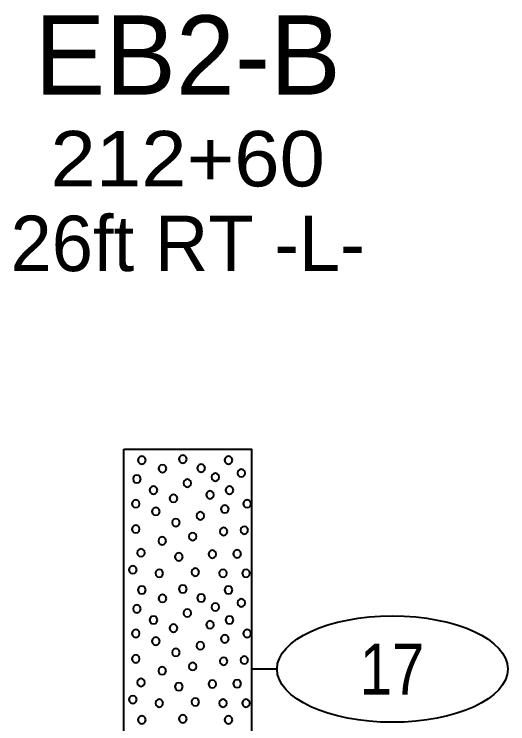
# Model space of a CAD drawing. Extents: x -582 to 653, y -817 to -3.
# Drawn here: x -482.55 to -472.9, y -185.68 to -171.8 of the extents above; entities that cross this region are included whole.
import ezdxf
from ezdxf.enums import TextEntityAlignment as Align

# ---------------------------------------------------------------- set-up
doc = ezdxf.new("R2010")
doc.units = 0
doc.header["$LTSCALE"] = 0.4
doc.layers.add('27', color=7, linetype='Continuous', lineweight=40)

msp = doc.modelspace()

# ---------------------------------------------------------------- linework, layer by layer
at = {"layer": '27'}
msp.add_line((-477.4109, -184.608), (-477.9109, -184.608), dxfattribs=at)
for points in [[(-480.4109, -180.308), (-477.9109, -180.308), (-477.9109, -206.808), (-480.4109, -206.808)], [(-479.979, -180.5207), (-479.9892, -180.4826), (-480.0171, -180.4547), (-480.0552, -180.4445), (-480.0933, -180.4547), (-480.1212, -180.4826), (-480.1314, -180.5207), (-480.1212, -180.5588), (-480.0933, -180.5867), (-480.0552, -180.5969), (-480.0171, -180.5867), (-479.9892, -180.5588)], [(-479.1781, -180.5011), (-479.1883, -180.463), (-479.2162, -180.4351), (-479.2543, -180.4249), (-479.2924, -180.4351), (-479.3202, -180.463), (-479.3305, -180.5011), (-479.3202, -180.5392), (-479.2924, -180.5671), (-479.2543, -180.5773), (-479.2162, -180.5671), (-479.1883, -180.5392)], [(-478.2844, -180.5207), (-478.2946, -180.4826), (-478.3225, -180.4548), (-478.3606, -180.4445), (-478.3987, -180.4548), (-478.4266, -180.4826), (-478.4368, -180.5207), (-478.4266, -180.5588), (-478.3987, -180.5867), (-478.3606, -180.5969), (-478.3225, -180.5867), (-478.2946, -180.5588)], [(-479.5741, -180.686), (-479.5843, -180.6479), (-479.6122, -180.62), (-479.6503, -180.6098), (-479.6884, -180.62), (-479.7163, -180.6479), (-479.7265, -180.686), (-479.7163, -180.7241), (-479.6884, -180.7519), (-479.6503, -180.7622), (-479.6122, -180.7519), (-479.5843, -180.7241)], [(-478.819, -180.677), (-478.8292, -180.6389), (-478.8571, -180.611), (-478.8952, -180.6008), (-478.9333, -180.611), (-478.9612, -180.6389), (-478.9714, -180.677), (-478.9612, -180.7151), (-478.9333, -180.743), (-478.8952, -180.7532), (-478.8571, -180.743), (-478.8292, -180.7151)], [(-478.0335, -180.7728), (-478.0438, -180.7347), (-478.0716, -180.7069), (-478.1097, -180.6966), (-478.1478, -180.7069), (-478.1757, -180.7347), (-478.1859, -180.7728), (-478.1757, -180.8109), (-478.1478, -180.8388), (-478.1097, -180.849), (-478.0716, -180.8388), (-478.0438, -180.8109)], [(-480.0752, -180.8885), (-480.0854, -180.8504), (-480.1133, -180.8225), (-480.1514, -180.8123), (-480.1895, -180.8225), (-480.2174, -180.8504), (-480.2276, -180.8885), (-480.2174, -180.9266), (-480.1895, -180.9545), (-480.1514, -180.9647), (-480.1133, -180.9545), (-480.0854, -180.9266)], [(-479.0891, -180.9717), (-479.0993, -180.9336), (-479.1272, -180.9057), (-479.1653, -180.8955), (-479.2034, -180.9057), (-479.2313, -180.9336), (-479.2415, -180.9717), (-479.2313, -181.0098), (-479.2034, -181.0377), (-479.1653, -181.0479), (-479.1272, -181.0377), (-479.0993, -181.0098)], [(-478.5408, -180.8542), (-478.551, -180.8161), (-478.5789, -180.7882), (-478.617, -180.778), (-478.6551, -180.7882), (-478.683, -180.8161), (-478.6932, -180.8542), (-478.683, -180.8923), (-478.6551, -180.9202), (-478.617, -180.9304), (-478.5789, -180.9202), (-478.551, -180.8923)], [(-479.7523, -181.1072), (-479.7625, -181.0691), (-479.7904, -181.0412), (-479.8285, -181.031), (-479.8666, -181.0412), (-479.8945, -181.0691), (-479.9047, -181.1072), (-479.8945, -181.1453), (-479.8666, -181.1732), (-479.8285, -181.1834), (-479.7904, -181.1732), (-479.7625, -181.1453)], [(-478.2636, -181.1072), (-478.2739, -181.0691), (-478.3017, -181.0412), (-478.3398, -181.031), (-478.3779, -181.0412), (-478.4058, -181.0691), (-478.416, -181.1072), (-478.4058, -181.1453), (-478.3779, -181.1732), (-478.3398, -181.1834), (-478.3017, -181.1732), (-478.2739, -181.1453)], [(-478.645, -181.2), (-478.6552, -181.1619), (-478.6831, -181.134), (-478.7212, -181.1238), (-478.7593, -181.134), (-478.7872, -181.1619), (-478.7974, -181.2), (-478.7872, -181.2381), (-478.7593, -181.266), (-478.7212, -181.2762), (-478.6831, -181.266), (-478.6552, -181.2381)], [(-480.0981, -181.3729), (-480.1083, -181.3348), (-480.1362, -181.3069), (-480.1743, -181.2967), (-480.2124, -181.3069), (-480.2403, -181.3348), (-480.2505, -181.3729), (-480.2403, -181.411), (-480.2124, -181.4389), (-480.1743, -181.4491), (-480.1362, -181.4389), (-480.1083, -181.411)], [(-479.3607, -181.2686), (-479.371, -181.2305), (-479.3988, -181.2027), (-479.4369, -181.1924), (-479.475, -181.2027), (-479.5029, -181.2305), (-479.5131, -181.2686), (-479.5029, -181.3067), (-479.475, -181.3346), (-479.4369, -181.3448), (-479.3988, -181.3346), (-479.371, -181.3067)], [(-477.9179, -181.3729), (-477.9281, -181.3348), (-477.956, -181.3069), (-477.9941, -181.2967), (-478.0322, -181.3069), (-478.06, -181.3348), (-478.0703, -181.3729), (-478.06, -181.411), (-478.0322, -181.4389), (-477.9941, -181.4491), (-477.956, -181.4389), (-477.9281, -181.411)], [(-479.7065, -181.5229), (-479.7167, -181.4848), (-479.7446, -181.4569), (-479.7827, -181.4467), (-479.8208, -181.4569), (-479.8487, -181.4848), (-479.8589, -181.5229), (-479.8487, -181.561), (-479.8208, -181.5889), (-479.7827, -181.5991), (-479.7446, -181.5889), (-479.7167, -181.561)], [(-478.3564, -181.4771), (-478.3667, -181.439), (-478.3945, -181.4111), (-478.4326, -181.4009), (-478.4707, -181.4111), (-478.4986, -181.439), (-478.5088, -181.4771), (-478.4986, -181.5152), (-478.4707, -181.5431), (-478.4326, -181.5533), (-478.3945, -181.5431), (-478.3667, -181.5152)], [(-478.8344, -181.6106), (-478.8447, -181.5725), (-478.8725, -181.5446), (-478.9106, -181.5344), (-478.9487, -181.5446), (-478.9766, -181.5725), (-478.9868, -181.6106), (-478.9766, -181.6487), (-478.9487, -181.6766), (-478.9106, -181.6868), (-478.8725, -181.6766), (-478.8447, -181.6487)], [(-479.3124, -181.7416), (-479.3226, -181.7035), (-479.3505, -181.6756), (-479.3886, -181.6654), (-479.4267, -181.6756), (-479.4546, -181.7035), (-479.4648, -181.7416), (-479.4546, -181.7797), (-479.4267, -181.8075), (-479.3886, -181.8178), (-479.3505, -181.8075), (-479.3226, -181.7797)], [(-480.0981, -181.8687), (-480.1083, -181.8306), (-480.1362, -181.8027), (-480.1743, -181.7925), (-480.2124, -181.8027), (-480.2403, -181.8306), (-480.2505, -181.8687), (-480.2403, -181.9068), (-480.2124, -181.9347), (-480.1743, -181.9449), (-480.1362, -181.9347), (-480.1083, -181.9068)], [(-478.3793, -181.9157), (-478.3895, -181.8776), (-478.4174, -181.8497), (-478.4555, -181.8395), (-478.4936, -181.8497), (-478.5215, -181.8776), (-478.5317, -181.9157), (-478.5215, -181.9538), (-478.4936, -181.9817), (-478.4555, -181.9919), (-478.4174, -181.9817), (-478.3895, -181.9538)], [(-477.9751, -181.8916), (-477.9853, -181.8535), (-478.0132, -181.8256), (-478.0513, -181.8154), (-478.0894, -181.8256), (-478.1173, -181.8535), (-478.1275, -181.8916), (-478.1173, -181.9297), (-478.0894, -181.9576), (-478.0513, -181.9678), (-478.0132, -181.9576), (-477.9853, -181.9297)], [(-478.9845, -182.0161), (-478.9947, -181.978), (-479.0226, -181.9502), (-479.0607, -181.9399), (-479.0988, -181.9502), (-479.1266, -181.978), (-479.1369, -182.0161), (-479.1266, -182.0542), (-479.0988, -182.0821), (-479.0607, -182.0923), (-479.0226, -182.0821), (-478.9947, -182.0542)], [(-479.5794, -182.1001), (-479.5896, -182.062), (-479.6175, -182.0341), (-479.6556, -182.0239), (-479.6937, -182.0341), (-479.7216, -182.062), (-479.7318, -182.1001), (-479.7216, -182.1382), (-479.6937, -182.166), (-479.6556, -182.1763), (-479.6175, -182.166), (-479.5896, -182.1382)], [(-479.9951, -182.3314), (-480.0053, -182.2933), (-480.0332, -182.2654), (-480.0713, -182.2552), (-480.1094, -182.2654), (-480.1373, -182.2933), (-480.1475, -182.3314), (-480.1373, -182.3695), (-480.1094, -182.3974), (-480.0713, -182.4076), (-480.0332, -182.3974), (-480.0053, -182.3695)], [(-478.5993, -182.3607), (-478.6095, -182.3226), (-478.6374, -182.2947), (-478.6755, -182.2845), (-478.7136, -182.2947), (-478.7414, -182.3226), (-478.7517, -182.3607), (-478.7414, -182.3988), (-478.7136, -182.4267), (-478.6755, -182.4369), (-478.6374, -182.4267), (-478.6095, -182.3988)], [(-478.1136, -182.353), (-478.1238, -182.3149), (-478.1517, -182.287), (-478.1898, -182.2768), (-478.2279, -182.287), (-478.2558, -182.3149), (-478.266, -182.353), (-478.2558, -182.3911), (-478.2279, -182.419), (-478.1898, -182.4292), (-478.1517, -182.419), (-478.1238, -182.3911)], [(-479.2565, -182.4115), (-479.2667, -182.3734), (-479.2946, -182.3455), (-479.3327, -182.3353), (-479.3708, -182.3455), (-479.3987, -182.3734), (-479.4089, -182.4115), (-479.3987, -182.4496), (-479.3708, -182.4775), (-479.3327, -182.4877), (-479.2946, -182.4775), (-479.2667, -182.4496)], [(-480.1566, -182.6645), (-480.1668, -182.6264), (-480.1947, -182.5985), (-480.2328, -182.5883), (-480.2709, -182.5985), (-480.2988, -182.6264), (-480.309, -182.6645), (-480.2988, -182.7026), (-480.2709, -182.7305), (-480.2328, -182.7407), (-480.1947, -182.7305), (-480.1668, -182.7026)], [(-479.6379, -182.7344), (-479.6481, -182.6963), (-479.676, -182.6684), (-479.7141, -182.6582), (-479.7522, -182.6684), (-479.7801, -182.6963), (-479.7903, -182.7344), (-479.7801, -182.7725), (-479.7522, -182.8004), (-479.7141, -182.8106), (-479.676, -182.8004), (-479.6481, -182.7725)], [(-478.9336, -182.7115), (-478.9438, -182.6734), (-478.9717, -182.6455), (-479.0098, -182.6353), (-479.0479, -182.6455), (-479.0758, -182.6734), (-479.086, -182.7115), (-479.0758, -182.7496), (-479.0479, -182.7775), (-479.0098, -182.7877), (-478.9717, -182.7775), (-478.9438, -182.7496)], [(-478.3908, -182.7344), (-478.401, -182.6963), (-478.4289, -182.6684), (-478.467, -182.6582), (-478.5051, -182.6684), (-478.533, -182.6963), (-478.5432, -182.7344), (-478.533, -182.7725), (-478.5051, -182.8004), (-478.467, -182.8106), (-478.4289, -182.8004), (-478.401, -182.7725)], [(-477.9407, -182.7344), (-477.9509, -182.6963), (-477.9788, -182.6684), (-478.0169, -182.6582), (-478.055, -182.6684), (-478.0829, -182.6963), (-478.0931, -182.7344), (-478.0829, -182.7725), (-478.055, -182.8004), (-478.0169, -182.8106), (-477.9788, -182.8004), (-477.9509, -182.7725)], [(-479.1781, -183.0411), (-479.1883, -183.003), (-479.2162, -182.9751), (-479.2543, -182.9649), (-479.2924, -182.9751), (-479.3202, -183.003), (-479.3305, -183.0411), (-479.3202, -183.0792), (-479.2924, -183.1071), (-479.2543, -183.1173), (-479.2162, -183.1071), (-479.1883, -183.0792)], [(-479.979, -183.0607), (-479.9892, -183.0226), (-480.0171, -182.9947), (-480.0552, -182.9845), (-480.0933, -182.9947), (-480.1212, -183.0226), (-480.1314, -183.0607), (-480.1212, -183.0988), (-480.0933, -183.1267), (-480.0552, -183.1369), (-480.0171, -183.1267), (-479.9892, -183.0988)], [(-478.2844, -183.0607), (-478.2946, -183.0226), (-478.3225, -182.9948), (-478.3606, -182.9845), (-478.3987, -182.9948), (-478.4266, -183.0226), (-478.4368, -183.0607), (-478.4266, -183.0988), (-478.3987, -183.1267), (-478.3606, -183.1369), (-478.3225, -183.1267), (-478.2946, -183.0988)], [(-479.5741, -183.226), (-479.5843, -183.1879), (-479.6122, -183.16), (-479.6503, -183.1498), (-479.6884, -183.16), (-479.7163, -183.1879), (-479.7265, -183.226), (-479.7163, -183.2641), (-479.6884, -183.2919), (-479.6503, -183.3022), (-479.6122, -183.2919), (-479.5843, -183.2641)], [(-478.819, -183.217), (-478.8292, -183.1789), (-478.8571, -183.151), (-478.8952, -183.1408), (-478.9333, -183.151), (-478.9612, -183.1789), (-478.9714, -183.217), (-478.9612, -183.2551), (-478.9333, -183.283), (-478.8952, -183.2932), (-478.8571, -183.283), (-478.8292, -183.2551)], [(-478.0335, -183.3128), (-478.0438, -183.2747), (-478.0716, -183.2469), (-478.1097, -183.2366), (-478.1478, -183.2469), (-478.1757, -183.2747), (-478.1859, -183.3128), (-478.1757, -183.3509), (-478.1478, -183.3788), (-478.1097, -183.389), (-478.0716, -183.3788), (-478.0438, -183.3509)], [(-480.0752, -183.4285), (-480.0854, -183.3904), (-480.1133, -183.3625), (-480.1514, -183.3523), (-480.1895, -183.3625), (-480.2174, -183.3904), (-480.2276, -183.4285), (-480.2174, -183.4666), (-480.1895, -183.4945), (-480.1514, -183.5047), (-480.1133, -183.4945), (-480.0854, -183.4666)], [(-478.5408, -183.3942), (-478.551, -183.3561), (-478.5789, -183.3282), (-478.617, -183.318), (-478.6551, -183.3282), (-478.683, -183.3561), (-478.6932, -183.3942), (-478.683, -183.4323), (-478.6551, -183.4602), (-478.617, -183.4704), (-478.5789, -183.4602), (-478.551, -183.4323)], [(-479.0891, -183.5117), (-479.0993, -183.4736), (-479.1272, -183.4457), (-479.1653, -183.4355), (-479.2034, -183.4457), (-479.2313, -183.4736), (-479.2415, -183.5117), (-479.2313, -183.5498), (-479.2034, -183.5777), (-479.1653, -183.5879), (-479.1272, -183.5777), (-479.0993, -183.5498)], [(-479.7523, -183.6472), (-479.7625, -183.6091), (-479.7904, -183.5812), (-479.8285, -183.571), (-479.8666, -183.5812), (-479.8945, -183.6091), (-479.9047, -183.6472), (-479.8945, -183.6853), (-479.8666, -183.7132), (-479.8285, -183.7234), (-479.7904, -183.7132), (-479.7625, -183.6853)], [(-478.645, -183.74), (-478.6552, -183.7019), (-478.6831, -183.674), (-478.7212, -183.6638), (-478.7593, -183.674), (-478.7872, -183.7019), (-478.7974, -183.74), (-478.7872, -183.7781), (-478.7593, -183.806), (-478.7212, -183.8162), (-478.6831, -183.806), (-478.6552, -183.7781)], [(-478.2636, -183.6472), (-478.2739, -183.6091), (-478.3017, -183.5812), (-478.3398, -183.571), (-478.3779, -183.5812), (-478.4058, -183.6091), (-478.416, -183.6472), (-478.4058, -183.6853), (-478.3779, -183.7132), (-478.3398, -183.7234), (-478.3017, -183.7132), (-478.2739, -183.6853)], [(-479.3607, -183.8086), (-479.371, -183.7705), (-479.3988, -183.7427), (-479.4369, -183.7324), (-479.475, -183.7427), (-479.5029, -183.7705), (-479.5131, -183.8086), (-479.5029, -183.8467), (-479.475, -183.8746), (-479.4369, -183.8848), (-479.3988, -183.8746), (-479.371, -183.8467)], [(-480.0981, -183.9129), (-480.1083, -183.8748), (-480.1362, -183.8469), (-480.1743, -183.8367), (-480.2124, -183.8469), (-480.2403, -183.8748), (-480.2505, -183.9129), (-480.2403, -183.951), (-480.2124, -183.9789), (-480.1743, -183.9891), (-480.1362, -183.9789), (-480.1083, -183.951)], [(-478.3564, -184.0171), (-478.3667, -183.979), (-478.3945, -183.9511), (-478.4326, -183.9409), (-478.4707, -183.9511), (-478.4986, -183.979), (-478.5088, -184.0171), (-478.4986, -184.0552), (-478.4707, -184.0831), (-478.4326, -184.0933), (-478.3945, -184.0831), (-478.3667, -184.0552)], [(-477.9179, -183.9129), (-477.9281, -183.8748), (-477.956, -183.8469), (-477.9941, -183.8367), (-478.0322, -183.8469), (-478.06, -183.8748), (-478.0703, -183.9129), (-478.06, -183.951), (-478.0322, -183.9789), (-477.9941, -183.9891), (-477.956, -183.9789), (-477.9281, -183.951)], [(-479.7065, -184.0629), (-479.7167, -184.0248), (-479.7446, -183.9969), (-479.7827, -183.9867), (-479.8208, -183.9969), (-479.8487, -184.0248), (-479.8589, -184.0629), (-479.8487, -184.101), (-479.8208, -184.1289), (-479.7827, -184.1391), (-479.7446, -184.1289), (-479.7167, -184.101)], [(-478.8344, -184.1506), (-478.8447, -184.1125), (-478.8725, -184.0846), (-478.9106, -184.0744), (-478.9487, -184.0846), (-478.9766, -184.1125), (-478.9868, -184.1506), (-478.9766, -184.1887), (-478.9487, -184.2166), (-478.9106, -184.2268), (-478.8725, -184.2166), (-478.8447, -184.1887)], [(-479.3124, -184.2816), (-479.3226, -184.2435), (-479.3505, -184.2156), (-479.3886, -184.2054), (-479.4267, -184.2156), (-479.4546, -184.2435), (-479.4648, -184.2816), (-479.4546, -184.3197), (-479.4267, -184.3475), (-479.3886, -184.3578), (-479.3505, -184.3475), (-479.3226, -184.3197)], [(-480.0981, -184.4087), (-480.1083, -184.3706), (-480.1362, -184.3427), (-480.1743, -184.3325), (-480.2124, -184.3427), (-480.2403, -184.3706), (-480.2505, -184.4087), (-480.2403, -184.4468), (-480.2124, -184.4747), (-480.1743, -184.4849), (-480.1362, -184.4747), (-480.1083, -184.4468)], [(-477.9751, -184.4316), (-477.9853, -184.3935), (-478.0132, -184.3656), (-478.0513, -184.3554), (-478.0894, -184.3656), (-478.1173, -184.3935), (-478.1275, -184.4316), (-478.1173, -184.4697), (-478.0894, -184.4976), (-478.0513, -184.5078), (-478.0132, -184.4976), (-477.9853, -184.4697)], [(-478.9845, -184.5561), (-478.9947, -184.518), (-479.0226, -184.4902), (-479.0607, -184.4799), (-479.0988, -184.4902), (-479.1266, -184.518), (-479.1369, -184.5561), (-479.1266, -184.5942), (-479.0988, -184.6221), (-479.0607, -184.6323), (-479.0226, -184.6221), (-478.9947, -184.5942)], [(-478.3793, -184.4557), (-478.3895, -184.4176), (-478.4174, -184.3897), (-478.4555, -184.3795), (-478.4936, -184.3897), (-478.5215, -184.4176), (-478.5317, -184.4557), (-478.5215, -184.4938), (-478.4936, -184.5217), (-478.4555, -184.5319), (-478.4174, -184.5217), (-478.3895, -184.4938)], [(-479.5794, -184.6401), (-479.5896, -184.602), (-479.6175, -184.5741), (-479.6556, -184.5639), (-479.6937, -184.5741), (-479.7216, -184.602), (-479.7318, -184.6401), (-479.7216, -184.6782), (-479.6937, -184.706), (-479.6556, -184.7163), (-479.6175, -184.706), (-479.5896, -184.6782)], [(-479.9951, -184.8714), (-480.0053, -184.8333), (-480.0332, -184.8054), (-480.0713, -184.7952), (-480.1094, -184.8054), (-480.1373, -184.8333), (-480.1475, -184.8714), (-480.1373, -184.9095), (-480.1094, -184.9374), (-480.0713, -184.9476), (-480.0332, -184.9374), (-480.0053, -184.9095)], [(-479.2565, -184.9515), (-479.2667, -184.9134), (-479.2946, -184.8855), (-479.3327, -184.8753), (-479.3708, -184.8855), (-479.3987, -184.9134), (-479.4089, -184.9515), (-479.3987, -184.9896), (-479.3708, -185.0175), (-479.3327, -185.0277), (-479.2946, -185.0175), (-479.2667, -184.9896)], [(-478.5993, -184.9007), (-478.6095, -184.8626), (-478.6374, -184.8347), (-478.6755, -184.8245), (-478.7136, -184.8347), (-478.7414, -184.8626), (-478.7517, -184.9007), (-478.7414, -184.9388), (-478.7136, -184.9667), (-478.6755, -184.9769), (-478.6374, -184.9667), (-478.6095, -184.9388)], [(-478.1136, -184.893), (-478.1238, -184.8549), (-478.1517, -184.827), (-478.1898, -184.8168), (-478.2279, -184.827), (-478.2558, -184.8549), (-478.266, -184.893), (-478.2558, -184.9311), (-478.2279, -184.959), (-478.1898, -184.9692), (-478.1517, -184.959), (-478.1238, -184.9311)], [(-480.1566, -185.2045), (-480.1668, -185.1664), (-480.1947, -185.1385), (-480.2328, -185.1283), (-480.2709, -185.1385), (-480.2988, -185.1664), (-480.309, -185.2045), (-480.2988, -185.2426), (-480.2709, -185.2705), (-480.2328, -185.2807), (-480.1947, -185.2705), (-480.1668, -185.2426)], [(-479.6379, -185.2744), (-479.6481, -185.2363), (-479.676, -185.2084), (-479.7141, -185.1982), (-479.7522, -185.2084), (-479.7801, -185.2363), (-479.7903, -185.2744), (-479.7801, -185.3125), (-479.7522, -185.3404), (-479.7141, -185.3506), (-479.676, -185.3404), (-479.6481, -185.3125)], [(-478.9336, -185.2515), (-478.9438, -185.2134), (-478.9717, -185.1855), (-479.0098, -185.1753), (-479.0479, -185.1855), (-479.0758, -185.2134), (-479.086, -185.2515), (-479.0758, -185.2896), (-479.0479, -185.3175), (-479.0098, -185.3277), (-478.9717, -185.3175), (-478.9438, -185.2896)], [(-478.3908, -185.2744), (-478.401, -185.2363), (-478.4289, -185.2084), (-478.467, -185.1982), (-478.5051, -185.2084), (-478.533, -185.2363), (-478.5432, -185.2744), (-478.533, -185.3125), (-478.5051, -185.3404), (-478.467, -185.3506), (-478.4289, -185.3404), (-478.401, -185.3125)], [(-477.9407, -185.2744), (-477.9509, -185.2363), (-477.9788, -185.2084), (-478.0169, -185.1982), (-478.055, -185.2084), (-478.0829, -185.2363), (-478.0931, -185.2744), (-478.0829, -185.3125), (-478.055, -185.3404), (-478.0169, -185.3506), (-477.9788, -185.3404), (-477.9509, -185.3125)], [(-479.979, -185.6007), (-479.9892, -185.5626), (-480.0171, -185.5347), (-480.0552, -185.5245), (-480.0933, -185.5347), (-480.1212, -185.5626), (-480.1314, -185.6007), (-480.1212, -185.6388), (-480.0933, -185.6667), (-480.0552, -185.6769), (-480.0171, -185.6667), (-479.9892, -185.6388)], [(-479.1781, -185.5811), (-479.1883, -185.543), (-479.2162, -185.5151), (-479.2543, -185.5049), (-479.2924, -185.5151), (-479.3202, -185.543), (-479.3305, -185.5811), (-479.3202, -185.6192), (-479.2924, -185.6471), (-479.2543, -185.6573), (-479.2162, -185.6471), (-479.1883, -185.6192)], [(-478.2844, -185.6007), (-478.2946, -185.5626), (-478.3225, -185.5348), (-478.3606, -185.5245), (-478.3987, -185.5348), (-478.4266, -185.5626), (-478.4368, -185.6007), (-478.4266, -185.6388), (-478.3987, -185.6667), (-478.3606, -185.6769), (-478.3225, -185.6667), (-478.2946, -185.6388)]]:
    msp.add_lwpolyline(points, close=True, dxfattribs=at)
msp.add_ellipse((-475.1535, -184.608), major_axis=(2.2574, 0), ratio=0.461538, dxfattribs=at)

# ---------------------------------------------------------------- texts
for s, height, p in [('EB2-B', 1.55, (-479.1591, -173.3685)), ('26ft RT -L-', 1.085, (-479.1587, -176.8219))]:
    msp.add_text(s, height=height, dxfattribs=at).set_placement(p, align=Align.CENTER)
for s, height, width, p in [('212+60', 1.085, 1.1, (-479.1582, -175.1649)), ('17', 1, 0.85, (-475.161, -185.108))]:
    msp.add_text(s, height=height, dxfattribs=dict(at, width=width)).set_placement(p, align=Align.CENTER)

doc.saveas('drawing.dxf')
